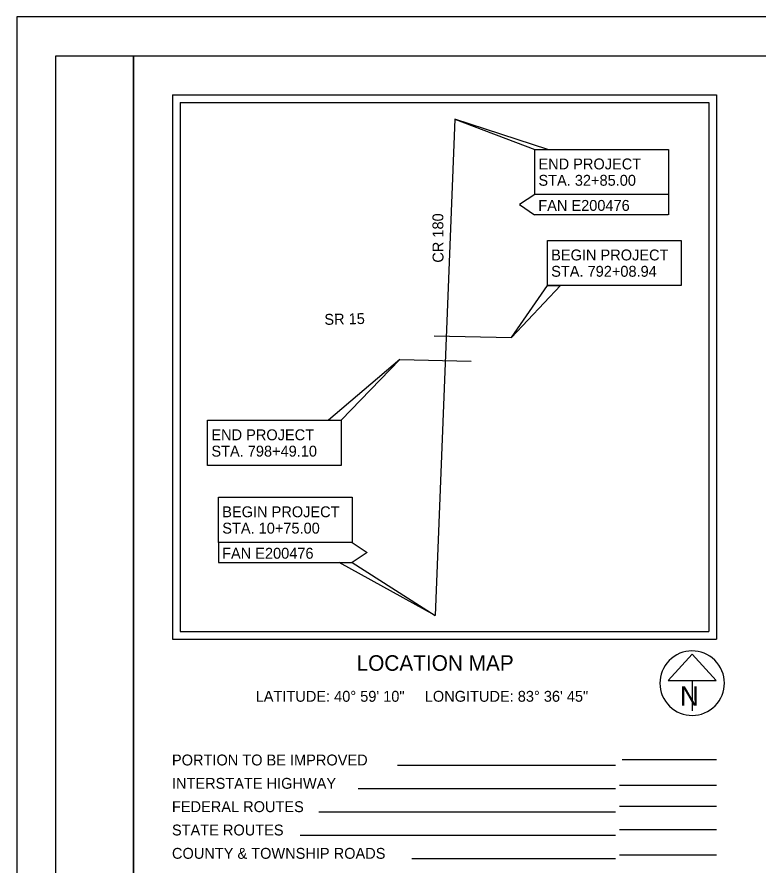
# Model space of a CAD drawing. Extents: x 0 to 45.5, y 0 to 22.
# Drawn here: x 0 to 9.53, y 11.1 to 22 of the extents above; entities that cross this region are included whole.
import ezdxf

# ---------------------------------------------------------------- set-up
doc = ezdxf.new("R2010")
doc.units = 0
for name, color, linetype in [('SH_Border', 7, 'Continuous'), ('SH_Cut_Line', 7, 'Continuous'), ('SH_Data', 7, 'Continuous')]:
    doc.layers.add(name, color=color, linetype=linetype)

msp = doc.modelspace()

# ---------------------------------------------------------------- linework, layer by layer
at = {"layer": 'SH_Border'}
for points in [[(0.5, 21.5), (1.5, 21.5), (1.5, 0.5), (0.5, 0.5)], [(1.5, 21.5), (33.5, 21.5), (33.5, 0.5), (1.5, 0.5)]]:
    msp.add_lwpolyline(points, close=True, dxfattribs=at)
at = {"layer": 'SH_Cut_Line'}
msp.add_lwpolyline([(0, 0), (34, 0), (34, 22), (0, 22)], close=True, dxfattribs=at)
at = {"layer": 'SH_Data'}
for p, q in [((2, 21), (9, 21)), ((2, 21), (2, 14)), ((9, 21), (9, 14)), ((2.1, 20.9), (2.1, 14.1)), ((2.1, 20.9), (8.9, 20.9)), ((8.9, 20.9), (8.9, 14.1)), ((5.634, 20.688), (5.378, 14.306)), ((6.66, 19.717), (6.465, 19.588)), ((8.379, 19.717), (8.379, 19.455)), ((6.465, 19.588), (6.659, 19.458)), ((8.378, 19.455), (6.659, 19.458)), ((5.367, 17.899), (6.361, 17.877)), ((4.923, 17.598), (5.842, 17.575)), ((2.593, 15.248), (2.593, 14.986)), ((4.312, 15.245), (4.507, 15.115)), ((4.507, 15.115), (4.312, 14.986)), ((2.593, 14.986), (4.312, 14.986)), ((2.1, 14.1), (8.9, 14.1)), ((2, 14), (9, 14)), ((8.685, 13.809), (8.377, 13.468)), ((8.992, 13.468), (8.685, 13.809)), ((8.377, 13.468), (8.992, 13.468)), ((8.685, 13.468), (8.685, 13.081)), ((8.685, 13.435), (8.685, 13.435)), ((8.685, 13.435), (8.685, 13.435)), ((7.783, 12.455), (9, 12.455)), ((7.7, 12.377), (4.894, 12.377)), ((9, 12.121), (7.75, 12.121)), ((7.7, 12.077), (4.39, 12.077)), ((7.7, 11.777), (3.885, 11.777)), ((9, 11.849), (7.75, 11.849)), ((7.7, 11.477), (3.645, 11.477)), ((9, 11.549), (7.75, 11.549)), ((7.7, 11.177), (5.078, 11.177)), ((9, 11.222), (7.75, 11.222))]:
    msp.add_line(p, q, dxfattribs=at)
for points in [[(6.83, 20.298), (5.634, 20.688), (6.66, 20.298)], [(6.66, 20.298), (8.379, 20.298), (8.379, 19.717), (6.66, 19.717)], [(6.824, 19.128), (8.543, 19.128), (8.543, 18.547), (6.824, 18.547)], [(6.99, 18.547), (6.361, 17.877), (6.824, 18.547)], [(4.172, 16.816), (4.923, 17.598), (4.006, 16.816)], [(2.453, 16.816), (4.172, 16.816), (4.172, 16.235), (2.453, 16.235)], [(2.593, 15.826), (4.312, 15.826), (4.312, 15.245), (2.593, 15.245)], [(4.312, 14.986), (5.378, 14.306), (4.146, 14.986)]]:
    msp.add_lwpolyline(points, close=True, dxfattribs=at)
msp.add_arc((8.685, 13.435), 0.415, 129.7798, 129.7633, dxfattribs=at)

# ---------------------------------------------------------------- texts
for s, height, p in [('END PROJECT', 0.14, (6.708, 20.04)), ('STA. 32+85.00', 0.14, (6.708, 19.83)), ('FAN E200476', 0.14, (6.706, 19.507)), ('BEGIN PROJECT', 0.14, (6.872, 18.87)), ('STA. 792+08.94', 0.14, (6.872, 18.66)), ('END PROJECT', 0.14, (2.501, 16.558)), ('STA. 798+49.10', 0.14, (2.501, 16.348)), ('BEGIN PROJECT', 0.14, (2.641, 15.568)), ('STA. 10+75.00', 0.14, (2.641, 15.358)), ('FAN E200476', 0.14, (2.639, 15.035)), ('LOCATION MAP', 0.2, (4.369, 13.594)), ('LATITUDE: 40° 59\' 10"     LONGITUDE: 83° 36\' 45"', 0.14, (3.071, 13.196)), ('N', 0.25, (8.529, 13.144)), ('PORTION TO BE IMPROVED', 0.14, (1.994, 12.377)), ('INTERSTATE HIGHWAY', 0.14, (1.994, 12.077)), ('FEDERAL ROUTES', 0.14, (1.994, 11.777)), ('STATE ROUTES', 0.14, (1.994, 11.477)), ('COUNTY & TOWNSHIP ROADS', 0.14, (1.994, 11.177))]:
    msp.add_text(s, height=height, dxfattribs=at).set_placement(p)
for s, rotation, p in [('CR 180', 90.2482, (5.487, 18.841)), ('SR 15', 1.3626, (3.956, 18.041))]:
    msp.add_text(s, height=0.14, rotation=rotation, dxfattribs=at).set_placement(p)

doc.saveas('drawing.dxf')
